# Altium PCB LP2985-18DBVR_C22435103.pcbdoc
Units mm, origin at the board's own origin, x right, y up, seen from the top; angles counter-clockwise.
Board outline 16.4 x 15.8 mm, 2 copper layers (Top Layer, Bottom Layer), stack 0 mm thick; 1 components, 0 nets, 5 pads, 0 vias.
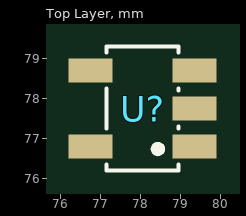
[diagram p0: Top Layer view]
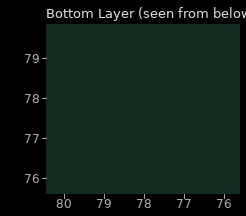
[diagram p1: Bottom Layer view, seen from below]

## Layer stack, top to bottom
Top Layer: signal copper (thickness not stored)
Bottom Layer: signal copper (thickness not stored)

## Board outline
86.25,69.85 69.85,69.85 69.85,85.65 86.25,85.65

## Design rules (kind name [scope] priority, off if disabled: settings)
PasteMaskExpansion "Paste Mask Expansion" [All] p1: expansion=0
SolderMaskExpansion "Solder Mask Expansion" [IsVia] p1: expansion=-25.4 istentingtop=TRUE
SolderMaskExpansion "Solder Mask Expansion" [All] p2: expansion=0.051 istentingtop=FALSE

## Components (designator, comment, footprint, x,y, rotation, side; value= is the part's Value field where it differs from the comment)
U? "LP2985-18DBVR" SOT-23-5_L3.0-W1.7-P0.95-LS2.8-BR 78.05,77.75 r0 top

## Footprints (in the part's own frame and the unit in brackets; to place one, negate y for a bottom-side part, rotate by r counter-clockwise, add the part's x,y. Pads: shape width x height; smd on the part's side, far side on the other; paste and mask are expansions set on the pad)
SOT-23-5_L3.0-W1.7-P0.95-LS2.8-BR [mm]
  rect 1.1x0.6 smd: 1(1.3,-0.95) 2(1.3,0) 3(1.3,0.95) 4(-1.3,0.95) 5(-1.3,-0.95)
  silkscreen extent -0.9,-1.55 0.9,1.55

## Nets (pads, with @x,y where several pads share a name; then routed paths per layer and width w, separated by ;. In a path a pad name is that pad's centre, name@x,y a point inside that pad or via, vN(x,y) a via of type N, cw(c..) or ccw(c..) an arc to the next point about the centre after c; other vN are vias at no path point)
pads on no net: U?.1 U?.2 U?.3 U?.4 U?.5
